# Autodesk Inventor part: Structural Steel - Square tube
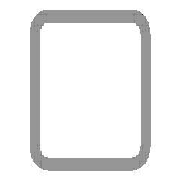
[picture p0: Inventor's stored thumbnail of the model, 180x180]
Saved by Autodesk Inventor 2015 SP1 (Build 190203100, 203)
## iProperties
_CCFamilyMember: 2
_CCFamilyDisplayName: ISO 4019 (Square) - Structural steels - Cold-formed, welded, structural hollow sections
_FrameMemberDoc: Frame Member File
_Version: 15.0.0
_GetPNFromCC: 1
Created: 2011-06
Part Number: Structural Steel - Square tube
Material: Stainless Steel
Document SubType Name: Modeling
Standard: ISO
Designer: Guilherme Augusto Franco de Souza
Standard Revision: Second edition 2001-09-01
Standards Organization: ISO
Language: en-US
Size Designation: 25x25x2
Categories: <MemberInstance><Categories><Category DisplayName="Structural Shapes" InternalName="089c4875-fa83-4c05-b084-43b9cc11f5ed" Mnemonic="GRDR"><CategoryParameter Dis
Stock Number: 25x25x2
Density: 8.08 g/cm^3
Description: ISO 4019 - 25x25x2
Appearance: Steel
G_L: 225,000 mm
G_W: 25,000 mm
G_H: 25,000 mm
+7BA6D68B-4ACB-437B-AEF3-661DB70B6601+CUTDETAIL1: Miter 45,00 deg
+408DD344-A613-4312-A56D-282087A78E9F+CUTDETAIL2: Cut
IsCustomPart: 1
Author: Guilherme Augusto Franco de Souza
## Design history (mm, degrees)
node "Start plane"
node "End plane"
sketch "Sketch"
  geometry: L1 (-12.5, -8.5)-(-12.5, 8.5); L2 (-8.5, 12.5)-(8.5, 12.5); L3 (12.5, 8.5)-(12.5, -8.5); L4 (8.5, -12.5)-(-8.5, -12.5); L5 (-8.5, 10.5)-(8.5, 10.5); L6 (10.5, 8.5)-(10.5, -8.5); L7 (8.5, -10.5)-(-8.5, -10.5); L8 (-10.5, -8.5)-(-10.5, 8.5); L9 (0, 18.66)-(0, -18.66) reference; L10 (-18.66, 0)-(18.66, 0) reference; A1 r 4 centre (-8.5, -8.5) between (-12.5, -8.5) and (-8.5, -12.5); A2 r 4 centre (8.5, 8.5) between (12.5, 8.5) and (8.5, 12.5); A3 r 4 centre (-8.5, 8.5) between (-8.5, 12.5) and (-12.5, 8.5); A4 r 4 centre (8.5, -8.5) between (8.5, -12.5) and (12.5, -8.5); A5 r 2 centre (-8.5, 8.5) between (-8.5, 10.5) and (-10.5, 8.5); A6 r 2 centre (8.5, 8.5) between (10.5, 8.5) and (8.5, 10.5); A7 r 2 centre (8.5, -8.5) between (8.5, -10.5) and (10.5, -8.5); A8 r 2 centre (-8.5, -8.5) between (-10.5, -8.5) and (-8.5, -10.5)
  constraints: 16 end point, 16 point on circle, 8 centre point, 8 tangent, 4 parallel, 3 equal radius, 2 perpendicular, 7 other
  dimensions: "d7" = 4 radius of A1 (= G_IR); "d9" = 25 distance between parallel lines of L1 L3 (= G_W); "d11" = 25 distance between parallel lines of L2 L4 (= G_H); "d12" = 2 distance between parallel lines of L3 L6 (= G_T); "d15" = 12.5 distance between parallel lines of L9 L3 (= 0.5 x d9); "d16" = 12.5 distance between parallel lines of L2 L10 (= 0.5 x d11)
extrude "Body" new body sketch "Sketch" stored distance "d3" = 225 (= G_L); taper "d4" = 0 deg
node "Driven Length"
  sketch "Sketch3"
    geometry: L1 (0, 0)-(10, 0) reference
    constraints: 2 end point, 1 horizontal
  workplane "Work Plane3"
  sketch "Sketch4"
    geometry: L1 (-2, 25)-(12, 25) reference; L2 (-2, 224.859)-(12, 224.859) reference
    dimensions: "d18" = 199.85858 distance between parallel lines of L1 L2 (derived)
workplane "Work Plane4"
split "Split1"
workplane "Work Plane5"
split "Split2"
body "Solid1"
other parameters: "G_W" = 25 [user parameter; used in 1 equation term], "G_H" = 25 [user parameter; used in 1 equation term], "G_T" = 2 [user parameter; used in 1 equation term], "G_IR" = 4 [user parameter; used in 1 equation term], "G_L" = 225 [user parameter; used in 1 equation term], "G_OFFSET_START" = -25 [user parameter; used in 1 equation term], "G_OFFSET_END" = -0.14142 [user parameter; used in 1 equation term], "d13" = 25 (= -G_OFFSET_START), "d14" = 224.85858 (= G_OFFSET_END + B_L), "B_L" = 225 [user parameter; used in 1 equation term], "d17" = 90 deg, "MAS" = 0.136 [user parameter]
